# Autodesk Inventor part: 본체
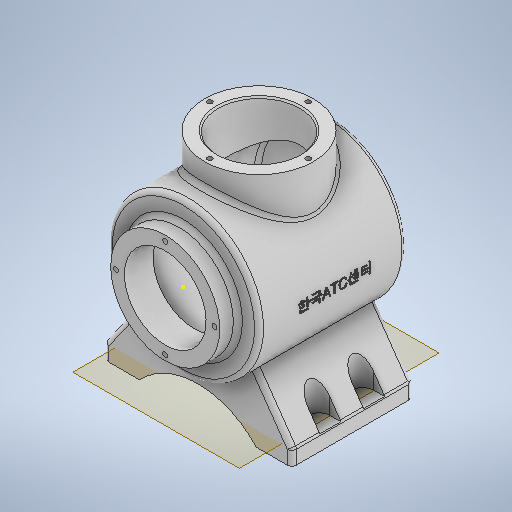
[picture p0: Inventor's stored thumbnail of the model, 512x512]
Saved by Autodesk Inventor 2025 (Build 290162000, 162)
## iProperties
Created: 2024-07
Part Number: 본체
Material: 일반
Document SubType Name: Modeling
Designer: 학생
Density: 1 g/cm^3
Appearance: 기본값
Author: 학생
## Parameters: d3 = 72 mm, d4 = 12 mm, d5 = 0, d6 = 65 mm, d26 = 226 mm, d28 = 108 mm, d29 = 90 deg, d31 = 62 mm, d32 = 72 mm, d33 = 12 mm, d34 = 0, d35 = 3 mm, d36 = -77 mm, d37 = 124 mm, d39 = 77 mm, d41 = 0, d42 = 77 mm, d43 = 124 mm, d45 = -54 mm, d46 = 55 deg, d48 = 0, d49 = 0, d50 = 0, d51 = 0, d52 = 17 mm, d55 = 0, d62 = 360 deg, d63 = 3 mm, d64 = 54 mm, d65 = 11 mm, d66 = 4 mm, d67 = 2 mm, d68 = 90 deg, d69 = 8 mm, d70 = 0, d71 = 3 mm, d72 = 1 mm, d73 = 2 mm, d74 = 45 deg, d75 = 3.242 mm, d76 = 8 mm, d77 = 4 mm, d78 = 2 mm, d79 = 90 deg, d81 = 120 deg, d82 = 65 mm, d83 = 65 mm, d84 = 3.242 mm, d85 = 8 mm, d86 = 4 mm, d87 = 2 mm, d88 = 90 deg, d90 = 120 deg, d91 = 65 mm, d92 = 65 mm, d93 = 127 mm, d94 = 62 mm, d95 = 0.5 mm, d96 = 0, d97 = 0.5 mm, d98 = 2 mm, d99 = 0, d106 = 43 mm, d107 = 19 mm, d108 = 27 mm, d110 = 7 mm, d111 = 7 mm, d112 = 7 mm, d113 = 212.12189 mm, d115 = 14 mm, d116 = 14 mm, d117 = 132 mm, d118 = 0, d119 = 3 mm, d120 = 3 mm, d121 = 14.5 mm
